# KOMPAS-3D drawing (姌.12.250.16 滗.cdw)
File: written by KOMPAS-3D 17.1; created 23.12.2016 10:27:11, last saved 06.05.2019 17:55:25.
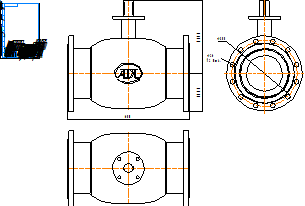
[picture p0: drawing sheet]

Sheet 1: A4, portrait

Title block, sheet 1: name: КШ.12.250.16 фф; material: Внимание! Данный продукт является объектом авторского права ООО «Торговый Дом АДЛ». / Запрещается изменение, копирование, распространение / (в том числе путем копирования на другие сайты и ресурсы в Интернете) / или любое иное использование информации и объектов без предварительного / согласия правообладателя (ООО «Торговый Дом АДЛ»).; sheets: 1; organisation: ООО "Торговый дом АДЛ"; sheet format: A4; stored path: C:\Users\tra\Desktop\2д чертежи\Шаровые краны БИВАЛ\КШ_Бивал_серия_11_12\KOMPAS_2D\КШ.12.250.16 фф.cdw

Views: Вид 1, Проекционный вид 2, Проекционный вид 3
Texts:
  Klimkovich
  ADL
Dimensions and other numbers on the sheet: 650; 389,5; 202,5; 355; 26; 12 Отв.; 1:1; 1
